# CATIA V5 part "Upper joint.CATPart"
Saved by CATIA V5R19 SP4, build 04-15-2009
Part number: Upper joint
Bounding box of the stored display mesh (mm): x 0 to 110, y -20 to 20, z -12.5 to 12.5
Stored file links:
  G:\EU_thinkMotion\CFAO_2010\MMS_groupe1\MMS_groupe1\OK\ptangsittisin\TANGSITTISIN\TANGSITTISIN\Upper joint.CATPart
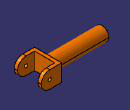
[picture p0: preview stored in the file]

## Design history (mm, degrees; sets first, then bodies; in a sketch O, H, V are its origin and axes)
Body1 (main body)
  Sketch1 on yz-plane, origin (0, 0, 0), H (0, 1, 0), V (0, 0, 1)
    circle A1 centre (0, 0) radius 10
    radius A1 = 10
  Pad1: profile Sketch1, direction (1, 0, 0), length 80
  Sketch2 on end face of Pad1, origin (80, 0, 0), H (0, 1, 0), V (0, 0, 1)
    line L1 (-20, 12.5) -> (20, 12.5)
    line L2 (20, 12.5) -> (20, -12.5)
    line L3 (20, -12.5) -> (-20, -12.5)
    line L4 (-20, -12.5) -> (-20, 12.5)
    length L2 = 25
    distance H L1 = 12.5
  Pad2: profile Sketch2, direction (1, 0, 0), length 30
  Sketch3 on face of Pad2 from Sketch2.L3, origin (0, 0, -12.5), H (1, 0, 0), V (0, -1, 0)
    reference projected curve E1 from face of Pad2 from Sketch2.L3
    line L1 (85, 15) -> (110, 15)
    line L2 (110, 15) -> (110, -15)
    line L3 (110, -15) -> (85, -15)
    line L4 (85, -15) -> (85, 15)
    length L4 = 30
    distance L1 H = 15
    length L3 = 25
    distance L2 E1 = 0
    length L1 = 25
  Pocket1: profile Sketch3, direction (0, 0, 1), through (limit type 6)
  Fillet1: radius 12.5, on edge [face of Pad2 from Sketch2.L1 | end face of Pad2] (x2); edge [face of Pad2 from Sketch2.L3 | end face of Pad2] (x2)
  Sketch4 on face of Pad2 from Sketch2.L4, origin (0, -20, 0), H (1, 0, 0), V (0, 0, 1)
    circle A1 centre (97.5, 0) radius 2.5
    radius A1 = 2.5
  Pocket2: profile Sketch4, direction (0, 1, 0), through (limit type 3)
